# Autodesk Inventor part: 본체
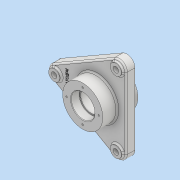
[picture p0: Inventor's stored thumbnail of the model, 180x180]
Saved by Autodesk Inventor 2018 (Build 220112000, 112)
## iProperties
Created: 2023-04
Part Number: 본체
Material: ABS 플라스틱
Document SubType Name: Modeling
Designer: home
Density: 1.06 g/cm^3
Appearance: 매끄러움 - 흰색
Mass: 478.584 g
Surface Area: 640.875 cm^2
Volume: 451.494 cm^3
Author: home
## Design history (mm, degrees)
sketch "스케치1" dims "d0" = 57
  geometry: L1 (-33, 84.87)-(90, 13.856); L2 (90, -13.856)-(-33, -84.87); L3 (-57, -71.014)-(-57, 71.014); A1 r 16 centre (82, 0) between (90, -13.856) and (90, 13.856); A2 r 16 centre (-41, 71.014) between (-33, 84.87) and (-57, 71.014); A3 r 16 centre (-41, -71.014) between (-57, -71.014) and (-33, -84.87); 7 further points
  constraints: 6 end point, 6 point on circle, 6 point on line, 6 tangent, 3 centre point, 2 coincident, 2 equal radius, 1 horizontal alignment, 1 midpoint, 9 other
  dimensions: "d1" = 16 radius of A1
extrude "돌출1" new body sketch "스케치1" distance "d2" = 18; taper "d3" = 0 deg
sketch "스케치2"
  geometry: C1 r 45 at (0, 0); 1 further point
  constraints: 1 centre point, 1 coincident
  dimensions: "d5" = 90 diameter of C1
extrude "돌출2" join sketch "스케치2" distance "d6" = 5; taper "d7" = 0 deg
node "작업 평면1"
sketch "스케치3"
  geometry: C1 r 40 at (0, 0); 1 further point
  constraints: 1 centre point, 1 coincident
  dimensions: "d9" = 80 diameter of C1
extrude "돌출3" join sketch "스케치3" distance "d10" = 70; taper "d11" = 0 deg
sketch "스케치4"
  geometry: L1 (-90, -13.856)-(33, -84.87) reference; L2 (57, -71.014)-(57, 71.014) reference; L3 (33, 84.87)-(-90, 13.856) reference; C1 r 40 at (0, 0) reference; C2 r 40 at (0, 0) reference; C3 r 11 at (-82, 0); C4 r 11 at (41, -71.014); C5 r 11 at (41, 71.014); A1 r 16 centre (41, -71.014) between (33, -84.87) and (57, -71.014) reference; A2 r 16 centre (41, 71.014) between (57, 71.014) and (33, 84.87) reference; A3 r 16 centre (-82, 0) between (-90, 13.856) and (-90, -13.856) reference; 1 further point
  constraints: 3 centre point, 2 coincident
  dimensions: "d13" = 22 diameter of C3; "d14" = 22 diameter of C4; "d15" = 22 diameter of C5
extrude "돌출4" join sketch "스케치4" distance "d16" = 4; taper "d17" = 0 deg
hole "구멍1" diameter "d20" = 11; stored, may be unused: countersink angle "d24" = 90 deg, drill point angle "d26" = 118 deg; dims "d18" = 10, "d19" = 10, "d21" = 6, "d22" = 4, "d23" = 2, "d25" = 8
hole "구멍2" diameter "d29" = 11; stored, may be unused: countersink angle "d33" = 90 deg, drill point angle "d35" = 118 deg; dims "d27" = 10, "d28" = 10, "d30" = 6, "d31" = 4, "d32" = 2, "d34" = 8
hole "구멍3" diameter "d38" = 11; stored, may be unused: countersink angle "d42" = 90 deg, drill point angle "d44" = 118 deg; dims "d36" = 10, "d37" = 10, "d39" = 6, "d40" = 4, "d41" = 2, "d43" = 8
hole "구멍4" diameter "d47" = 42; stored, may be unused: countersink angle "d51" = 90 deg, drill point angle "d53" = 118 deg; dims "d45" = 10, "d46" = 10, "d48" = 6, "d49" = 47, "d50" = 17, "d52" = 70
hole "구멍5" diameter "d56" = 42; stored, may be unused: countersink angle "d60" = 90 deg, drill point angle "d62" = 118 deg; dims "d54" = 10, "d55" = 10, "d57" = 6, "d58" = 47, "d59" = 17, "d61" = 70
sketch "스케치5"
  geometry: A1 r 32 centre (0, 0) between (-32, 0) and (0, -32); 3 further points
  constraints: 4 point on circle, 1 centre point, 1 coincident
  dimensions: "d63" = 64 diameter of A1
hole "구멍6" sketch "스케치5" at (-32, 0), (0, -32), (32, 0), (0, 32) diameter "d64" = 3.242; stored, may be unused: countersink angle "d68" = 90 deg, drill point angle "d70" = 118 deg; dims "d65" = 8, "d66" = 47, "d67" = 17, "d69" = 10
sketch "스케치6"
  geometry: C1 r 1.621 at (-32, 0) reference; C2 r 1.621 at (32, 0) reference; A1 r 32 centre (0, 0) between (0, -32) and (0, 32); 3 further points
  constraints: 3 coincident, 2 point on circle, 1 centre point
  dimensions: "d71" = 64 diameter of A1
hole "구멍7" sketch "스케치6" at (-32, 0), (0, -32), (32, 0), (0, 32) diameter "d72" = 3.242; stored, may be unused: countersink angle "d76" = 90 deg, drill point angle "d78" = 118 deg; dims "d73" = 8, "d74" = 47, "d75" = 17, "d77" = 10
fillet "모깎기1" dims "d79" = 3
fillet "모깎기2" dims "d80" = 3
fillet "모깎기3" dims "d81" = 3
fillet "모깎기4" dims "d82" = 0.6
chamfer "모따기1" distance "d83" = 1; stored, may be unused: second distance "d84" = 2, angle "d85" = 45 deg
fillet "모깎기5" dims "d86" = 3
sketch "스케치7"
  geometry: 2 further points
  constraints: 1 horizontal alignment, 1 other
  dimensions: "d87" = 60 distance of point (-60, 0) point (0, 0)
feature "엠보싱1" sketch "스케치7" dims "d0" = 57, "d1" = 16, "d88" = 0.5, "d89" = 0
node "솔리드1"
node "투영된 루프1"
node "투영된 루프2"
other parameters: "d8" = 18
